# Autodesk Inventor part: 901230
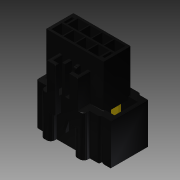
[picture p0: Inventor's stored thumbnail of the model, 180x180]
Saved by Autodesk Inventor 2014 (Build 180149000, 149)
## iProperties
Created: 2007-10
Part Number: 901230
Document SubType Name: Modeling
Designer: TT
Density: 1.06 g/cm^3
Mass: 6.30275 g
Surface Area: 103.939 cm^2
Volume: 5.94599 cm^3
Material: ABS Plastic
Description: R34 MOTOR CONNECTOR
Appearance: Glossy - Black
Component Category: Electrical
Author: TT
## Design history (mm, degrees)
sketch "Sketch1"
  geometry: L1 (-12.573, 5.969)-(12.573, 5.969); L2 (12.573, 5.969)-(12.573, -5.969); L3 (12.573, -5.969)-(-12.573, -5.969); L4 (-12.573, -5.969)-(-12.573, 5.969); L5 (-11.303, 4.191)-(-10.287, 4.191); L6 (-10.287, 4.191)-(-10.287, 0.381); L7 (-10.287, 0.381)-(-11.303, 0.381); L8 (-11.303, 0.381)-(-11.303, 4.191); L9 (-9.525, 4.953)-(-4.699, 4.953); L10 (-4.699, 4.953)-(-4.699, 0.381); L11 (-4.699, 0.381)-(-9.525, 0.381); L12 (-9.525, 0.381)-(-9.525, 4.953); L13 (-4.191, 4.953)-(0.635, 4.953); L14 (0.635, 4.953)-(0.635, 0.381); L15 (0.635, 0.381)-(-4.191, 0.381); L16 (-4.191, 0.381)-(-4.191, 4.953); L17 (1.143, 4.953)-(5.969, 4.953); L18 (5.969, 4.953)-(5.969, 0.381); L19 (5.969, 0.381)-(1.143, 0.381); L20 (1.143, 0.381)-(1.143, 4.953); L21 (6.477, 4.953)-(11.303, 4.953); L22 (11.303, 4.953)-(11.303, 0.381); L23 (11.303, 0.381)-(6.477, 0.381); L24 (6.477, 0.381)-(6.477, 4.953); L25 (10.287, -0.379)-(11.303, -0.379); L26 (11.303, -0.379)-(11.303, -4.189); L27 (11.303, -4.189)-(10.287, -4.189); L28 (10.287, -4.189)-(10.287, -0.379); L29 (4.699, -0.379)-(9.525, -0.379); L30 (9.525, -0.379)-(9.525, -4.953); L31 (9.525, -4.953)-(4.699, -4.953); L32 (4.699, -4.953)-(4.699, -0.379); L33 (-0.635, -0.379)-(4.191, -0.379); L34 (4.191, -0.379)-(4.191, -4.953); L35 (4.191, -4.953)-(-0.635, -4.953); L36 (-0.635, -4.953)-(-0.635, -0.379); L37 (-5.969, -0.379)-(-1.143, -0.379); L38 (-1.143, -0.379)-(-1.143, -4.953); L39 (-1.143, -4.953)-(-5.969, -4.953); L40 (-5.969, -4.953)-(-5.969, -0.379); L41 (-11.303, -0.379)-(-6.477, -0.379); L42 (-6.477, -0.379)-(-6.477, -4.953); L43 (-6.477, -4.953)-(-11.303, -4.953); L44 (-11.303, -4.953)-(-11.303, -0.379); 2 further points
  constraints: 88 end point, 22 parallel, 13 collinear, 11 horizontal, 11 perpendicular, 1 coincident
  dimensions: "d0" = 25.146 distance of L1.start L1.end; "d1" = 11.938 distance of L3.end L1.start; "d2" = 1.27 distance between parallel lines of L4 L8; "d3" = 1.778 distance between parallel lines of L1 L5; "d4" = 3.81 distance between parallel lines of L7 L5; "d5" = 1.016 distance of L5.start L5.end; "d6" = 0.762 distance between parallel lines of L12 L6; "d7" = 1.016 distance between parallel lines of L1 L9; "d8" = 4.826 distance between parallel lines of L12 L10; "d9" = 4.572 distance between parallel lines of L11 L9; "d11" = 0.508 distance between parallel lines of L16 L10; "d12" = 4.826 distance between parallel lines of L14 L16 (= d8); "d13" = 0.508 distance between parallel lines of L20 L14 (= d11); "d14" = 4.826 distance between parallel lines of L18 L20 (= d12); "d15" = 0.508 distance between parallel lines of L24 L18 (= d13); "d16" = 4.826 distance between parallel lines of L22 L24 (= d14); "d17" = 1.78 distance between parallel lines of L3 L27; "d18" = 1.016 distance between parallel lines of L3 L31; "d19" = 1.016 distance between parallel lines of L26 L28; "d20" = 1.27 distance between parallel lines of L2 L26; "d21" = 3.81 distance of L25.end L26.end; "d22" = 0.762 distance between parallel lines of L30 L28; "d23" = 4.826 distance between parallel lines of L32 L30; "d24" = 0.508 distance between parallel lines of L34 L32; "d25" = 4.826 distance of L34.end L35.end (= d23); "d26" = 0.508 distance between parallel lines of L38 L36 (= d24); "d27" = 4.826 distance between parallel lines of L40 L38 (= d25); "d28" = 0.508 distance between parallel lines of L40 L42 (= d26); "d29" = 4.826 distance between parallel lines of L44 L42 (= d27)
extrude "Extrusion1" new body sketch "Sketch1" distance "d30" = 18.669; taper "d31" = 0 deg
sketch "Sketch2"
  geometry: L1 (12.573, 5.969)-(-12.573, 5.969) reference; L2 (-12.573, 5.969)-(-12.573, -5.969) reference; L3 (12.573, -5.969)-(12.573, 5.969) reference; L4 (20.666, 0)-(-24.602, 0) reference; L5 (0, -15.733)-(0, 13.142) reference; L6 (-14.198, 9.017)-(14.199, 9.017); L7 (14.199, 9.017)-(14.199, -9.017); L8 (-18.135, -8.23)-(-18.135, 8.026); L9 (-14.198, 9.017)-(-14.198, 8.026); L10 (-14.198, 8.026)-(-18.135, 8.026); L11 (-18.135, -8.23)-(-14.134, -8.23); L12 (-14.134, -8.23)-(-14.134, -9.017); L13 (-14.134, -9.017)-(-9.6, -9.017); L14 (-9.6, -9.017)-(-9.6, -11.608); L15 (-2.996, -11.608)-(-2.996, -9.017); L16 (-2.996, -9.017)-(2.998, -9.017); L17 (2.998, -9.017)-(2.998, -11.608); L18 (9.602, -11.608)-(9.602, -9.017); L19 (9.602, -9.017)-(14.199, -9.017); L20 (9.602, -11.608)-(2.998, -11.608); L21 (-2.996, -11.608)-(-9.6, -11.608); L22 (-12.573, 4.998)-(-16.636, 4.998); L23 (-16.636, 4.998)-(-16.636, -5.202); L24 (-16.636, -5.202)-(-12.573, -5.202); L25 (-12.573, -5.202)-(-12.573, 4.998); 1 further point
  constraints: 40 end point, 7 horizontal, 6 vertical, 5 parallel, 3 collinear, 2 perpendicular, 1 point on line
  dimensions: "d47" = 1.626 distance between parallel lines of L7 L3; "d48" = 3.048 distance between parallel lines of L1 L6; "d49" = 28.397 distance between parallel lines of L7 L9; "d50" = 3.937 distance of L9.end L8.end; "d51" = 0.991 distance of L6.start L9.end; "d52" = 16.256 distance of L8.start L8.end; "d53" = 18.034 distance of L6.end L7.end; "d54" = 2.591 distance of L18.start L18.end; "d55" = 4.597 distance of L18.end L7.end; "d56" = 6.604 distance of L18.start L17.end; "d57" = 6.604 distance of L15.start L14.end (= d56); "d58" = 5.994 distance of L15.end L16.end; "d59" = 4.534 distance of L12.end L13.end; "d60" = 3.028 distance between parallel lines of L22 L10; "d61" = 10.2 distance of L22.end L23.end; "d62" = 1.499 distance between parallel lines of L23 L8
extrude "Extrusion2" join sketch "Sketch2" distance "d63" = 1.168; taper "d64" = 0 deg
sketch "Sketch3"
  geometry: L1 (14.199, 9.017)-(14.199, -9.017) reference; L2 (-14.198, 9.017)-(14.199, 9.017) reference; L3 (-14.198, 8.026)-(-14.198, 9.017) reference; L4 (-18.135, 8.026)-(-14.198, 8.026) reference; L5 (-18.135, -8.23)-(-18.135, 8.026) reference; L6 (-14.134, -8.23)-(-18.135, -8.23) reference; L7 (-14.134, -9.017)-(-14.134, -8.23) reference; L8 (-9.6, -9.017)-(-14.134, -9.017) reference; L9 (-9.6, -11.608)-(-9.6, -9.017) reference; L10 (-2.996, -11.608)-(-9.6, -11.608) reference; L11 (2.998, -9.017)-(-2.996, -9.017) reference; L12 (9.602, -11.608)-(2.998, -11.608) reference; L13 (9.602, -9.017)-(9.602, -11.608) reference; L14 (14.199, -9.017)-(9.602, -9.017) reference; L15 (-16.636, 6.527)-(-12.097, 6.527); L16 (-12.097, 6.527)-(-12.097, 7.518); L17 (-12.097, 7.518)-(12.7, 7.518); L18 (12.7, 7.518)-(12.7, -7.518); L19 (12.7, -7.518)-(8.103, -7.518); L20 (8.103, -7.518)-(8.103, -10.109); L21 (8.103, -10.109)-(6.477, -10.109); L22 (6.477, -10.109)-(6.477, -7.518); L23 (6.477, -7.518)-(-6.475, -7.518); L24 (-6.475, -7.518)-(-6.475, -10.109); L25 (-6.475, -10.109)-(-8.101, -10.109); L26 (-8.101, -10.109)-(-8.101, -7.505); L27 (-8.101, -7.505)-(-12.355, -7.505); L28 (-12.355, -7.505)-(-12.355, -6.731); L29 (-12.355, -6.731)-(-16.636, -6.731); L30 (-16.636, -6.731)-(-16.636, 6.527); L31 (-4.976, -11.608)-(-4.976, -9.017); L32 (-4.976, -9.017)-(4.978, -9.017); L33 (4.978, -9.017)-(4.978, -11.608)
  constraints: 38 end point, 10 vertical, 9 horizontal, 2 point on line
  dimensions: "d65" = 1.499 distance between parallel lines of L30 L5; "d66" = 1.499 distance between parallel lines of L4 L15; "d67" = 1.499 distance between parallel lines of L2 L17; "d68" = 1.499 distance between parallel lines of L1 L18; "d69" = 1.499 distance between parallel lines of L14 L19; "d70" = 1.499 distance between parallel lines of L11 L23; "d71" = 1.499 distance between parallel lines of L10 L25; "d72" = 1.499 distance between parallel lines of L12 L21; "d73" = 1.499 distance between parallel lines of L6 L29; "d74" = 1.626 distance between parallel lines of L24 L26; "d75" = 1.499 distance between parallel lines of L31 L24; "d76" = 1.499 distance between parallel lines of L26 L9; "d77" = 1.499 distance between parallel lines of L22 L33; "d78" = 1.626 distance between parallel lines of L20 L22; "d79" = 1.499 distance between parallel lines of L13 L20
extrude "Extrusion3" join sketch "Sketch3" distance "d80" = 16.815; taper "d81" = 0 deg
sketch "Sketch4"
  geometry: L1 (-14.199, 9.017)-(-14.199, -9.017) reference; L2 (-9.602, -11.608)-(-2.998, -11.608) reference; L3 (-2.998, -11.608)-(-2.998, -9.017) reference; L4 (-2.998, -9.017)-(2.996, -9.017) reference; L5 (2.996, -9.017)-(2.996, -11.608) reference; L6 (2.996, -11.608)-(9.6, -11.608) reference; L7 (-6.846, -5.969)-(-6.846, -11.608); L8 (-2.998, -9.957)-(-5.576, -9.957); L9 (-5.576, -9.957)-(-5.576, -5.969); L10 (-2.54, -5.969)-(-2.54, -9.017); L11 (-1.27, -9.017)-(-1.27, -5.969); L12 (1.27, -5.969)-(1.27, -9.017); L13 (-4.978, -9.017)-(4.976, -9.017) reference; L14 (2.54, -9.017)-(2.54, -5.969); L15 (5.575, -5.969)-(5.575, -9.957); L16 (5.575, -9.957)-(2.996, -9.957); L17 (6.845, -5.969)-(6.845, -11.608); 2 further points
  constraints: 20 end point, 8 point on line, 8 vertical, 2 horizontal, 1 collinear, 9 other
  dimensions: "d82" = 7.353 distance between parallel lines of L7 L1; "d83" = 1.651 distance between parallel lines of L8 L2; "d84" = 1.27 distance between parallel lines of L9 L7; "d85" = 11.659 distance between parallel lines of L10 L1; "d86" = 1.27 distance between parallel lines of L11 L10; "d87" = 2.54 distance between parallel lines of L12 L11; "d88" = 1.27 distance between parallel lines of L14 L12; "d89" = 3.035 distance between parallel lines of L15 L14; "d90" = 1.27 distance between parallel lines of L17 L15
extrude "Extrusion4" join sketch "Sketch4" distance "d91" = 12.37; taper "d92" = 0 deg
sketch "Sketch5"
  geometry: L1 (-7.974, -16.815)-(1.98, -16.815) reference; L2 (-3.505, -6.909)-(-2.489, -6.909); L3 (-2.489, -6.909)-(-2.489, -10.973); L4 (-2.489, -10.973)-(-3.505, -10.973); L5 (-3.505, -10.973)-(-3.505, -6.909); L6 (15.139, 1.168)-(15.139, -16.815) reference
  constraints: 8 end point, 2 parallel, 1 horizontal, 1 perpendicular
  dimensions: "d93" = 17.628 distance from line of L6 L2.end; "d94" = 1.016 distance between parallel lines of L3 L5; "d95" = 4.064 distance between parallel lines of L4 L2; "d96" = 5.842 distance between parallel lines of L1 L4
extrude "Extrusion5" join sketch "Sketch5" distance "d97" = 1.524; taper "d98" = 0 deg
sketch "Sketch6"
  geometry: L1 (-7.974, 0)-(-5.994, 0) reference; L2 (-7.974, 0)-(-7.974, -16.815) reference; L3 (1.98, 0)-(1.98, -16.815) reference; L4 (0, 0)-(1.98, 0) reference; L5 (-5.994, 0)-(-5.994, -5.842); L6 (-5.994, -5.842)-(-7.974, -5.842); L7 (0, 0)-(0, -5.842); L8 (0, -5.842)-(1.98, -5.842); L9 (-12.598, 1.168)-(-9.842, 1.168) reference
  constraints: 8 end point, 2 horizontal, 2 point on line, 2 vertical, 1 collinear
  dimensions: "d99" = 7.01 distance between parallel lines of L6 L9
extrude "Extrusion6" join sketch "Sketch6" distance "d100" = 2.591; taper "d101" = 0 deg
fillet "Fillet1" dims "d102" = 1.778, "d103" = 1.753, "d104" = 0.279, "d105" = 0.254
fillet "Fillet2" dims "d106" = 0.254, "d107" = 1.27
fillet "Fillet3" dims "d108" = 0.254, "d109" = 2.54
chamfer "Chamfer1" distance "d110" = 3; stored, may be unused: second distance "d111" = 2, angle "d112" = 26.57 deg
sketch "Sketch7"
  geometry: L1 (11.303, 0.381)-(11.303, 4.953) reference; L2 (11.303, 4.953)-(6.477, 4.953) reference; L3 (8.294, 4.251)-(9.487, 4.251); L4 (9.487, 4.251)-(9.487, 3.657); L5 (9.487, 3.657)-(10.491, 3.657); L6 (10.491, 3.657)-(10.491, 2.657); L7 (10.491, 2.657)-(9.897, 2.657); L8 (9.897, 2.657)-(9.897, 0.761); L9 (9.897, 0.761)-(7.883, 0.761); L10 (7.883, 0.761)-(7.883, 2.657); L11 (7.883, 2.657)-(7.29, 2.657); L12 (7.29, 2.657)-(7.29, 3.657); L13 (7.29, 3.657)-(8.294, 3.657); L14 (8.294, 3.657)-(8.294, 4.251)
  constraints: 24 end point, 6 horizontal, 6 vertical, 2 collinear
  dimensions: "d113" = 0.702 distance between parallel lines of L2 L3; "d114" = 0.594 distance between parallel lines of L13 L3; "d115" = 1 distance between parallel lines of L11 L13; "d116" = 1.896 distance between parallel lines of L9 L11; "d117" = 0.812 distance between parallel lines of L1 L6; "d118" = 1.004 distance between parallel lines of L6 L4; "d119" = 1.193 distance between parallel lines of L4 L14; "d120" = 1.004 distance between parallel lines of L12 L14; "d121" = 1.406 distance between parallel lines of L1 L8; "d122" = 2.014 distance between parallel lines of L8 L10
extrude "Extrusion7" cut sketch "Sketch7" stored distance "d123" = 2.591; taper "d124" = 0 deg
pattern_linear "Rectangular Pattern1" dims "d127" = 5.334
sketch "Sketch8"
  geometry: L1 (9.525, -4.953)-(9.525, -0.379) reference; L2 (4.699, -4.953)-(9.525, -4.953) reference; L3 (7.709, -4.251)-(7.709, -3.657); L4 (7.709, -3.657)-(8.713, -3.657); L5 (8.713, -3.657)-(8.713, -2.657); L6 (8.713, -2.657)-(8.119, -2.657); L7 (8.119, -2.657)-(8.119, -0.761); L8 (8.119, -0.761)-(6.105, -0.761); L9 (6.105, -0.761)-(6.105, -2.657); L10 (6.105, -2.657)-(5.512, -2.657); L11 (5.512, -2.657)-(5.512, -3.657); L12 (5.512, -3.657)-(6.516, -3.657); L13 (6.516, -3.657)-(6.516, -4.251); L14 (6.516, -4.251)-(7.709, -4.251)
  constraints: 24 end point, 6 horizontal, 6 vertical, 2 collinear
  dimensions: "d128" = 0.702 distance between parallel lines of L2 L14; "d129" = 0.594 distance between parallel lines of L4 L14; "d130" = 1 distance between parallel lines of L4 L6; "d131" = 1.896 distance between parallel lines of L8 L6; "d132" = 0.812 distance between parallel lines of L5 L1; "d133" = 1.004 distance between parallel lines of L3 L5; "d134" = 1.193 distance between parallel lines of L13 L3; "d135" = 1.004 distance between parallel lines of L11 L13; "d136" = 1.406 distance between parallel lines of L1 L7; "d137" = 2.014 distance between parallel lines of L9 L7
extrude "Extrusion8" cut sketch "Sketch8" stored distance "d138" = 2.591; taper "d139" = 0 deg
pattern_linear "Rectangular Pattern2" dims "d142" = 5.334
sketch "Sketch9"
  geometry: L1 (12.7, -7.518)-(12.7, 7.518) reference; L2 (-12.573, 4.998)-(-12.573, -5.202) reference; L3 (-11.303, 0.761)-(11.303, 0.761); L4 (11.303, 0.761)-(11.303, -0.761); L5 (11.303, -0.761)-(-11.303, -0.761); L6 (-11.303, -0.761)-(-11.303, 0.761); L7 (-11.303, -1.261)-(-10.287, -1.261); L8 (-10.287, -1.261)-(-10.287, -2.67); L9 (-10.287, -2.67)-(-11.303, -2.67); L10 (-11.303, -2.67)-(-11.303, -1.261); L11 (0, -15.735)-(0, 13.142) reference; L12 (20.666, 0)-(-24.602, 0) reference; L13 (11.303, 0.381)-(11.303, 4.191) reference; L14 (11.303, 1.261)-(10.287, 1.261); L15 (10.287, 1.261)-(10.287, 2.67); L16 (10.287, 2.67)-(11.303, 2.67); L17 (11.303, 2.67)-(11.303, 1.261); 1 further point
  constraints: 24 end point, 6 parallel, 3 horizontal, 3 perpendicular, 1 point on line
  dimensions: "d143" = 1.27 distance between parallel lines of L6 L2; "d144" = 1.397 distance between parallel lines of L1 L4; "d145" = 2.286 distance between parallel lines of L8 L2; "d146" = 0.5 distance between parallel lines of L7 L5; "d147" = 1.016 distance between parallel lines of L8 L10; "d148" = 1.409 distance between parallel lines of L9 L7; "d149" = 0.761 distance between parallel lines of L12 L5; "d150" = 1.016 distance between parallel lines of L15 L17; "d151" = 1.409 distance between parallel lines of L14 L16; "d152" = 0.5 distance between parallel lines of L3 L14
extrude "Extrusion9" cut sketch "Sketch9" distance "d153" = 1.168; taper "d154" = 0 deg
sketch "Sketch10"
  geometry: L1 (-11.276, -0.742)-(11.284, -0.742); L2 (11.284, -0.742)-(11.284, 0.024); L3 (11.284, 0.024)-(9.922, 0.024); L4 (9.922, 0.024)-(9.922, 0.753); L5 (9.922, 0.753)-(-9.922, 0.753); L6 (-9.922, 0.753)-(-9.922, 0.024); L7 (-9.922, 0.024)-(-11.276, 0.024); L8 (-11.276, 0.024)-(-11.276, -0.742); L9 (-11.303, 0.761)-(-9.897, 0.761) reference; L10 (-11.303, 4.953)-(-11.303, 0.381) reference; L11 (11.303, 0.381)-(11.303, 4.191) reference; L12 (11.303, 0.761)-(10.287, 0.761) reference
  constraints: 16 end point, 4 horizontal, 4 vertical
  dimensions: "d155" = 0.737 distance between parallel lines of L9 L7; "d156" = 1.381 distance between parallel lines of L10 L6; "d157" = 1.381 distance between parallel lines of L11 L4; "d158" = 0.737 distance between parallel lines of L12 L3
extrude "Extrusion10" join sketch "Sketch10" distance "d159" = 1.168; taper "d160" = 0 deg
sketch "Sketch12"
  geometry: L1 (-10.525, 3.689)-(-7.264, 3.689); L2 (-7.264, 3.689)-(-7.264, 2.626); L3 (-7.264, 2.626)-(-10.525, 2.626); L4 (-10.525, 2.626)-(-10.525, 3.689); L5 (5.499, 3.683)-(8.724, 3.683); L6 (8.724, 3.683)-(8.724, 2.657); L7 (8.724, 2.657)-(5.499, 2.657); L8 (5.499, 2.657)-(5.499, 3.683); L9 (-8.723, -2.64)-(-5.507, -2.64); L10 (-5.507, -2.64)-(-5.507, -3.666); L11 (-5.507, -3.666)-(-8.723, -3.666); L12 (-8.723, -3.666)-(-8.723, -2.64); L13 (-3.387, -2.647)-(-0.173, -2.647); L14 (-0.173, -2.647)-(-0.173, -3.664); L15 (-0.173, -3.664)-(-3.387, -3.664); L16 (-3.387, -3.664)-(-3.387, -2.647); L17 (1.95, -2.651)-(5.157, -2.651); L18 (5.157, -2.651)-(5.157, -3.658); L19 (5.157, -3.658)-(1.95, -3.658); L20 (1.95, -3.658)-(1.95, -2.651); L21 (7.283, -2.653)-(10.491, -2.653); L22 (10.491, -2.653)-(10.491, -3.658); L23 (10.491, -3.658)-(7.283, -3.658); L24 (7.283, -3.658)-(7.283, -2.653)
  constraints: 48 end point, 12 parallel, 6 horizontal, 6 perpendicular
extrude "Extrusion11" join sketch "Sketch12" distance "d161" = 10.332; taper "d162" = 0 deg
chamfer "Chamfer2" distance "d163" = 0.7; stored, may be unused: second distance "d164" = 2, angle "d165" = 1 deg
chamfer "Chamfer3" distance "d166" = 0.3; stored, may be unused: second distance "d167" = 2, angle "d168" = 1 deg
fillet "Fillet5" dims "d170" = 1.27
fillet "Fillet6" dims "d171" = 0.254
sketch "Sketch13"
  geometry: L1 (27.122, -0.558)-(26.685, 0); L2 (27.122, -0.558)-(27.558, 0); L3 (26.685, 0)-(27.558, 0)
  constraints: 6 end point, 1 horizontal
extrude "Extrusion12" cut sketch "Sketch13" stored distance "d174" = 1.168; taper "d175" = 0 deg
fillet "Fillet7" dims "d176" = 0.9
fillet "Fillet8" dims "d177" = 0.254
body "Solid1"
other parameters: "d178" = 0, "d179" = 0, "d180" = 0
